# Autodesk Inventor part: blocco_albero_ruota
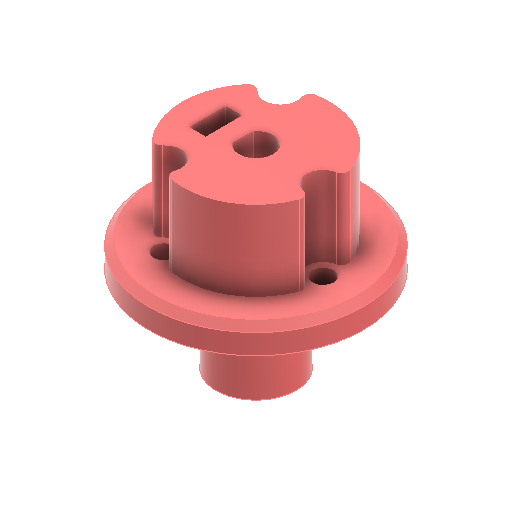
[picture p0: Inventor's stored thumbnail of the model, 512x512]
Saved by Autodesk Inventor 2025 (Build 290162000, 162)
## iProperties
Created: 2025-05
Part Number: blocco_albero_ruota
Material: Plastica ABS
Document SubType Name: Modeling
Designer: R5800u
Density: 1.06 g/cm^3
Appearance: Liscia - Rosso
Author: R5800u
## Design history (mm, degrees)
sketch "Schizzo1"
  geometry: L1 (0, 0)-(5.95, 0); L2 (5.95, 0)-(5.95, 12.8); L3 (5.95, 12.8)-(15.95, 12.8); L4 (15.95, 12.8)-(15.95, 16.8); L5 (15.95, 16.8)-(10.95, 16.8); L6 (10.95, 16.8)-(10.95, 28.8); L7 (10.95, 28.8)-(0, 28.8); L8 (0, 28.8)-(0, 0); L9 (2.55, 28.8)-(2.55, 0)
  constraints: 18 end point, 7 perpendicular, 2 horizontal, 2 point on line
  dimensions: "d0" = 5.95 distance of L1.start L1.end; "d1" = 12.8 distance of L1.end L2.end; "d2" = 10 distance of L2.end L3.end; "d3" = 4 distance of L3.end L4.end; "d4" = 5 distance of L4.end L5.end; "d5" = 12 distance of L5.end L6.end; "d6" = 2.55 distance between parallel lines of L8 L9
revolve "Rivoluzione1" sketch "Schizzo1" stored, may be unused: angle "d7" = 90 deg
sketch "Schizzo4"
  geometry: C1 r 1.6 at (10, 0) reference; C2 r 1.6 at (-5, -8.66) reference; C3 r 1.55 at (-5, 8.66) reference; 1 further point
extrude "Estrusione1" cut sketch "Schizzo4" extent not by distance; stored distance "d8" = 0; taper "d9" = 0 deg
sketch "Schizzo5"
  geometry: C1 r 1.6 at (0, 0) reference; C2 r 1.55 at (-15, 8.66) reference; C3 r 1.6 at (-15, -8.66) reference; 4 further points
  constraints: 3 coincident
hole "Foro1" sketch "Schizzo5" at (0, 0), (-15, 8.66), (-15, -8.66) diameter "d10" = 5; stored, may be unused: countersink angle "d14" = 90 deg, drill point angle "d16" = 0 deg; dims "d11" = 6, "d12" = 6.3, "d13" = 2, "d15" = 8
fillet "Raccordo1" dims "d17" = 1
sketch "Schizzo6"
  geometry: L1 (-2.021, -1.555)-(-1.979, 1.608); A1 r 2.55 centre (0, 0) between (-2.021, -1.555) and (-1.979, 1.608); 1 further point
  constraints: 2 end point, 2 point on circle, 1 centre point, 1 coincident
  dimensions: "d18" = 5.1 diameter of A1; "d19" = 2 distance from line of point (0, 0) L1
extrude "Estrusione2" join sketch "Schizzo6" distance "d20" = 20; taper "d21" = 0 deg
sketch "Schizzo7"
  geometry: L1 (-7.25, -2.75)-(-4.75, -2.75); L2 (-4.75, -2.75)-(-4.75, 2.75); L3 (-4.75, 2.75)-(-7.25, 2.75); L4 (-7.25, 2.75)-(-7.25, -2.75); L5 (-7.25, -2.75)-(-4.75, 2.75); L6 (-4.75, -2.75)-(-7.25, 2.75); 2 further points
  constraints: 12 end point, 2 midpoint, 2 parallel, 1 horizontal, 1 perpendicular
  dimensions: "d22" = 2.5 distance of L3.end L2.end; "d23" = 5.5 distance of L3.end L1.start; "d24" = 6 distance of point (0, 0) point (-6, 0)
extrude "Estrusione3" cut sketch "Schizzo7" distance "d25" = 12; taper "d26" = 0 deg
chamfer "Smusso1" distance "d27" = 1; stored, may be unused: second distance "d28" = 2, angle "d29" = 45 deg
sketch "Schizzo8"
  geometry: L1 (-8.701, 20)-(5.314, 20) reference; L2 (-1.694, 20)-(-1.582, 4); L3 (-7.532, 4)-(4.368, 4) reference; 2 further points
  constraints: 2 end point, 2 midpoint
  dimensions: "d30" = 7 distance from line of L1 point (-1.612, 13)
hole "Foro2" sketch "Schizzo8" at (-1.612, 13) diameter "d31" = 3.2; stored, may be unused: countersink angle "d35" = 90 deg, drill point angle "d37" = 0 deg; dims "d32" = 6, "d33" = 6.3, "d34" = 2, "d36" = 8
node "Solido1"
node "Riferimento4"
node "Riferimento5"
node "Riferimento6"
